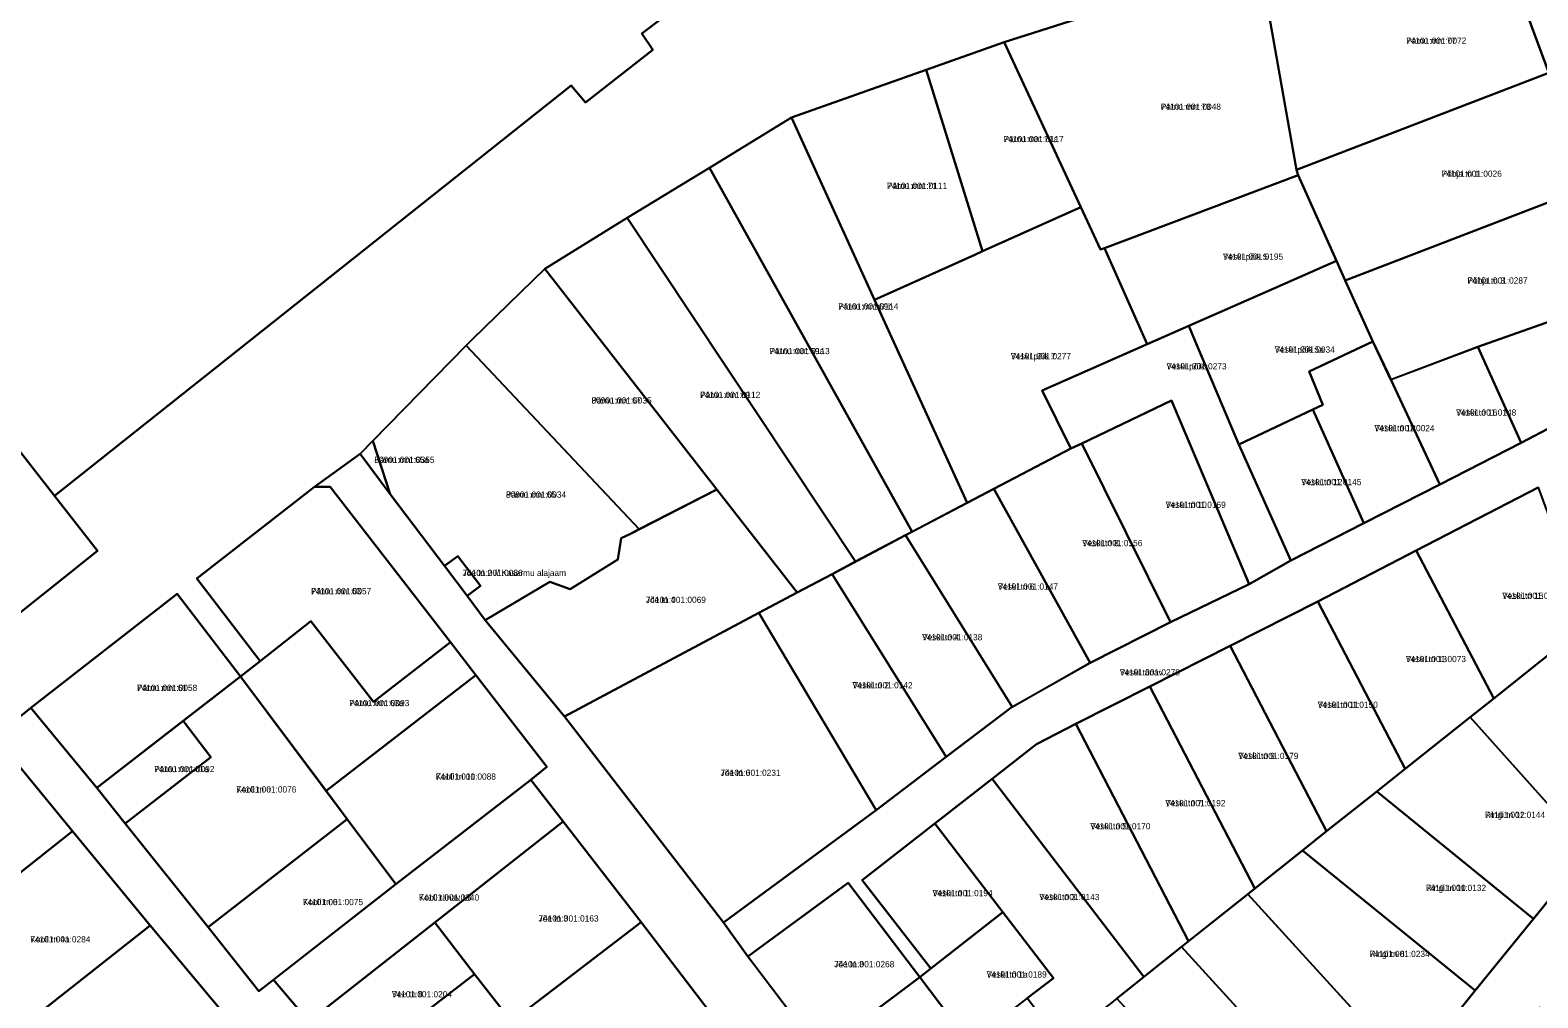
# Model space of a CAD drawing. Extents: x 524000 to 564260, y 6469338 to 6496391.
# Drawn here: x 538611.4 to 538974.9, y 6474369 to 6474602.3 of the extents above; entities that cross this region are included whole.
import ezdxf

# ---------------------------------------------------------------- set-up
doc = ezdxf.new("R2010")
doc.units = 0
for name, color, linetype in [('L_AADRESS', 7, 'Continuous'), ('PIIR', 7, 'Continuous'), ('TUNNUS', 7, 'Continuous')]:
    doc.layers.add(name, color=color, linetype=linetype)

msp = doc.modelspace()

# ---------------------------------------------------------------- linework, layer by layer
at = {"layer": 'PIIR'}
for points in [[(538977.59, 6474592), (538963.74, 6474629.42), (538971.75, 6474634.3), (538987.81, 6474590.76), (538994.7, 6474571.49), (539004.64, 6474545), (539014.72, 6474516.14), (539033.35, 6474462.51), (539027.05, 6474453.49), (539019.89, 6474474.48), (539007.32, 6474508.78), (539002.63, 6474519.46), (538996.03, 6474538.66), (538994.03, 6474544.04), (538987.03, 6474564.43)], [(538908.23, 6474616.82), (538963.74, 6474629.42), (538977.59, 6474592), (538916.78, 6474568.64)], [(538869.49, 6474549.4), (538846.25, 6474599.4), (538877.81, 6474609.46), (538908.23, 6474616.82), (538916.78, 6474568.64), (538917.16, 6474567.35), (538870.48, 6474549.77)], [(538846.25, 6474599.4), (538864.74, 6474559.62), (538841.01, 6474548.99), (538827.46, 6474592.74)], [(538827.46, 6474592.74), (538841.01, 6474548.99), (538839.19, 6474548.17), (538814.99, 6474537.32), (538795, 6474581.23)], [(538926.41, 6474546.71), (538917.16, 6474567.35), (538916.78, 6474568.64), (538977.59, 6474592), (538987.03, 6474564.43), (538928.49, 6474541.92)], [(538795, 6474581.23), (538814.99, 6474537.32), (538837.3, 6474488.32), (538824.03, 6474481.37), (538775.16, 6474569.14)], [(538775.16, 6474569.14), (538824.03, 6474481.37), (538822.42, 6474480.53), (538810.38, 6474474.16), (538755.33, 6474557.04)], [(538880.7, 6474526.56), (538870.48, 6474549.77), (538917.16, 6474567.35), (538926.41, 6474546.71), (538911.31, 6474540.02), (538890.78, 6474530.99)], [(538987.03, 6474564.43), (538994.03, 6474544.04), (538986.96, 6474541.66), (538988.92, 6474536.01), (538960.51, 6474525.92), (538939.48, 6474517.96), (538938.82, 6474519.38), (538935.17, 6474527.22), (538928.49, 6474541.92)], [(538864.74, 6474559.62), (538869.49, 6474549.4), (538870.48, 6474549.77), (538880.7, 6474526.56), (538855.4, 6474515.43), (538862.33, 6474501.42), (538843.78, 6474491.71), (538837.3, 6474488.32), (538814.99, 6474537.32), (538839.19, 6474548.17), (538841.01, 6474548.99)], [(538755.33, 6474557.04), (538810.38, 6474474.16), (538804.74, 6474471.17), (538796.35, 6474466.73), (538776.93, 6474491.57), (538735.48, 6474544.8)], [(538717.96, 6474527.75), (538735.48, 6474544.8), (538776.93, 6474491.57), (538758.26, 6474481.99), (538716.53, 6474526.3)], [(538892.33, 6474527.3), (538890.78, 6474530.99), (538911.31, 6474540.02), (538926.41, 6474546.71), (538928.49, 6474541.92), (538935.17, 6474527.22), (538919.76, 6474519.97), (538923.13, 6474511.97), (538920.67, 6474510.81), (538902.83, 6474502.37)], [(538970.95, 6474502.8), (538960.51, 6474525.92), (538988.92, 6474536.01), (538996.03, 6474538.66), (539002.63, 6474519.46)], [(538890.78, 6474530.99), (538892.33, 6474527.3), (538902.83, 6474502.37), (538915.35, 6474474.4), (538905.34, 6474468.72), (538886.57, 6474512.99), (538865.01, 6474502.62), (538862.33, 6474501.42), (538855.4, 6474515.43), (538880.7, 6474526.56)], [(538693.98, 6474503.28), (538716.53, 6474526.3), (538758.26, 6474481.99), (538755.96, 6474480.81), (538753.9, 6474479.81), (538753.05, 6474474.64), (538741.56, 6474467.55), (538736.69, 6474469.28), (538721.09, 6474460.07), (538716.71, 6474465.91), (538719.93, 6474468.3), (538714.51, 6474475.51), (538711.31, 6474473.12), (538698.2, 6474490.47), (538694.06, 6474503.04)], [(538920.67, 6474510.81), (538923.13, 6474511.97), (538919.76, 6474519.97), (538935.17, 6474527.22), (538938.84, 6474519.5), (538939.51, 6474518.1), (538951.3, 6474492.78), (538932.95, 6474483.42)], [(538939.51, 6474518.1), (538960.51, 6474525.92), (538970.95, 6474502.8), (538951.3, 6474492.78)], [(538544.83, 6474476), (538596.73, 6474516.27), (538617.2, 6474490.06), (538627.58, 6474476.75), (538576.39, 6474435.94)], [(538886.57, 6474512.99), (538905.34, 6474468.72), (538886.35, 6474459.58), (538865.01, 6474502.62)], [(538902.83, 6474502.37), (538920.67, 6474510.81), (538932.95, 6474483.42), (538915.35, 6474474.4)], [(538693.98, 6474503.28), (538698.2, 6474490.47), (538690.92, 6474500.18)], [(538865.01, 6474502.62), (538886.35, 6474459.58), (538867, 6474449.77), (538843.78, 6474491.71), (538862.33, 6474501.42)], [(538679.97, 6474492.17), (538683.68, 6474492.23), (538712.7, 6474454.73), (538694.12, 6474440.35), (538679.06, 6474459.77), (538666.8, 6474450.2), (538651.56, 6474470.07)], [(538796.35, 6474466.73), (538787.06, 6474461.85), (538740.26, 6474436.84), (538721.09, 6474460.07), (538736.69, 6474469.28), (538741.56, 6474467.55), (538753.05, 6474474.64), (538753.9, 6474479.81), (538755.96, 6474480.81), (538776.93, 6474491.57)], [(538837.3, 6474488.32), (538843.78, 6474491.71), (538867, 6474449.77), (538847.55, 6474438.66), (538848.21, 6474439.16), (538822.42, 6474480.53)], [(538945.62, 6474476.84), (538975.04, 6474492.07), (538985.81, 6474462.76), (538987.09, 6474459.29), (538964.31, 6474441.18)], [(538832.26, 6474427.06), (538804.74, 6474471.17), (538822.42, 6474480.53), (538848.21, 6474439.16)], [(538714.51, 6474475.51), (538719.93, 6474468.3), (538716.71, 6474465.91), (538711.31, 6474473.12)], [(538945.62, 6474476.84), (538964.31, 6474441.18), (538958.66, 6474436.69), (538942.98, 6474424.22), (538921.91, 6474464.57)], [(538796.35, 6474466.73), (538804.74, 6474471.17), (538832.26, 6474427.06), (538815.41, 6474414.27), (538787.06, 6474461.85)], [(538646.83, 6474466.37), (538662.08, 6474446.5), (538627.44, 6474419.6), (538611.51, 6474438.94)], [(538921.91, 6474464.57), (538942.98, 6474424.22), (538936.1, 6474418.76), (538924, 6474409.14), (538900.73, 6474453.86)], [(538740.26, 6474436.84), (538787.06, 6474461.85), (538815.41, 6474414.27), (538778.57, 6474387.15)], [(538712.7, 6474454.73), (538718.82, 6474446.82), (538682.73, 6474418.87), (538662.08, 6474446.5), (538666.8, 6474450.2), (538679.06, 6474459.77), (538694.12, 6474440.35)], [(538964.31, 6474441.18), (538987.09, 6474459.29), (539000.29, 6474420.56), (538987.35, 6474404.61), (538958.66, 6474436.69)], [(538881.4, 6474444.06), (538900.73, 6474453.86), (538924, 6474409.14), (538918.21, 6474404.53), (538906.69, 6474395.37)], [(538634.3, 6474411), (538654.9, 6474427), (538648.29, 6474435.79), (538662.08, 6474446.5), (538687.82, 6474412.06), (538654.26, 6474386)], [(538687.82, 6474412.06), (538682.73, 6474418.87), (538718.82, 6474446.82), (538735.95, 6474424.68), (538732.1, 6474421.56), (538699.57, 6474396.35)], [(538881.4, 6474444.06), (538906.69, 6474395.37), (538904.98, 6474394), (538890.71, 6474382.65), (538863.52, 6474435.09)], [(538627.44, 6474419.6), (538648.29, 6474435.79), (538654.9, 6474427), (538634.3, 6474411)], [(538942.98, 6474424.22), (538958.66, 6474436.69), (538987.35, 6474404.61), (538973.92, 6474388.05), (538936.1, 6474418.76)], [(538602.88, 6474431.92), (538621.59, 6474409.2), (538584.02, 6474379.46), (538566.97, 6474403.52)], [(538854.08, 6474430.11), (538863.52, 6474435.09), (538890.71, 6474382.65), (538889, 6474381.29), (538879.91, 6474374.06), (538843.32, 6474421.75)], [(538678.55, 6474363.31), (538670.05, 6474373.34), (538699.57, 6474396.35), (538732.1, 6474421.56), (538739.91, 6474411.48), (538708.99, 6474387.13)], [(538829.52, 6474411.02), (538843.32, 6474421.75), (538879.91, 6474374.06), (538873.38, 6474368.86), (538859.93, 6474358.17), (538851.8, 6474368.88), (538858.13, 6474373.74), (538845.95, 6474389.6)], [(538936.1, 6474418.76), (538973.92, 6474388.05), (538959.85, 6474370.72), (538918.21, 6474404.53), (538924, 6474409.14)], [(538699.57, 6474396.35), (538666.54, 6474370.61), (538654.26, 6474386), (538687.82, 6474412.06)], [(538718.49, 6474374.72), (538708.99, 6474387.13), (538739.91, 6474411.48), (538758.7, 6474387.21), (538727.46, 6474363.28)], [(538829.52, 6474411.02), (538845.95, 6474389.6), (538828.55, 6474376.07), (538811.98, 6474397.38)], [(538621.59, 6474409.2), (538640.34, 6474386.45), (538601, 6474355.48), (538592.29, 6474367.79), (538584.02, 6474379.46)], [(538906.69, 6474395.37), (538918.21, 6474404.53), (538959.85, 6474370.72), (538954.95, 6474364.67), (538942.26, 6474353.11), (538904.98, 6474394)], [(538808.62, 6474396.72), (538825.87, 6474373.98), (538801.88, 6474355.97), (538784.45, 6474378.94)], [(538904.98, 6474394), (538942.26, 6474353.11), (538927.21, 6474339.38), (538889, 6474381.29)], [(538825.87, 6474373.98), (538828.55, 6474376.07), (538845.95, 6474389.6), (538858.13, 6474373.74), (538851.8, 6474368.88), (538837.92, 6474358.11)], [(538640.34, 6474386.45), (538658.76, 6474364.28), (538617.77, 6474331.89), (538601, 6474355.48)], [(538678.55, 6474363.31), (538708.99, 6474387.13), (538718.49, 6474374.72), (538687.93, 6474351.07)], [(538737.46, 6474350.11), (538728.06, 6474362.51), (538727.46, 6474363.28), (538758.7, 6474387.21), (538777.23, 6474363), (538746, 6474339.05)], [(538889, 6474381.29), (538927.21, 6474339.38), (538912.49, 6474325.97), (538873.38, 6474368.86)], [(538687.93, 6474351.07), (538718.49, 6474374.72), (538727.46, 6474363.28), (538728.06, 6474362.51), (538697.33, 6474338.86)], [(538801.88, 6474355.97), (538825.87, 6474373.98), (538837.92, 6474358.11), (538813.97, 6474340.04)]]:
    msp.add_lwpolyline(points, close=True, dxfattribs=at)
for points in [[(538793.63, 6474627.81), (538758.87, 6474601.52), (538761.55, 6474597.57), (538745.3, 6474584.88), (538741.81, 6474589.01), (538617.2, 6474490.06), (538596.73, 6474516.27), (538557.75, 6474565.87), (538501.44, 6474521.28), (538496, 6474516.95), (538416.66, 6474453.86), (538401.82, 6474471.42)], [(538576.39, 6474435.94), (538627.58, 6474476.75), (538617.2, 6474490.06), (538741.81, 6474589.01), (538745.3, 6474584.88), (538761.55, 6474597.57), (538758.87, 6474601.52), (538793.63, 6474627.81)], [(538877.81, 6474609.46), (538846.25, 6474599.4), (538827.46, 6474592.74), (538795, 6474581.23), (538775.16, 6474569.14), (538755.33, 6474557.04), (538735.48, 6474544.8), (538717.96, 6474527.75), (538716.53, 6474526.3), (538693.98, 6474503.28), (538690.92, 6474500.18), (538679.97, 6474492.17), (538651.56, 6474470.07), (538666.8, 6474450.2), (538662.08, 6474446.5), (538646.83, 6474466.37), (538611.51, 6474438.94), (538602.88, 6474431.92)], [(538975.04, 6474492.07), (538945.62, 6474476.84), (538921.91, 6474464.57), (538900.73, 6474453.86), (538881.4, 6474444.06), (538863.52, 6474435.09), (538854.08, 6474430.11), (538843.32, 6474421.75), (538829.52, 6474411.02), (538811.98, 6474397.38), (538828.55, 6474376.07), (538825.87, 6474373.98), (538808.62, 6474396.72), (538784.45, 6474378.94), (538778.57, 6474387.15), (538815.41, 6474414.27), (538832.26, 6474427.06), (538848.21, 6474439.16), (538867, 6474449.77), (538886.35, 6474459.58), (538905.34, 6474468.72), (538915.35, 6474474.4), (538932.95, 6474483.42), (538951.3, 6474492.78), (538970.95, 6474502.8), (539002.63, 6474519.46)], [(538777.23, 6474363), (538758.7, 6474387.21), (538739.91, 6474411.48), (538732.1, 6474421.56), (538735.95, 6474424.68), (538718.82, 6474446.82), (538712.7, 6474454.73), (538683.68, 6474492.23), (538679.97, 6474492.17), (538690.92, 6474500.18), (538698.2, 6474490.47), (538711.31, 6474473.12), (538716.71, 6474465.91), (538721.09, 6474460.07), (538740.26, 6474436.84), (538778.57, 6474387.15), (538784.45, 6474378.94), (538785.84, 6474377.1), (538801.88, 6474355.97)], [(538658.76, 6474364.28), (538640.34, 6474386.45), (538621.59, 6474409.2), (538602.88, 6474431.92), (538611.51, 6474438.94), (538627.44, 6474419.6), (538634.3, 6474411), (538654.26, 6474386), (538666.54, 6474370.61), (538670.05, 6474373.34), (538678.55, 6474363.31)], [(538975.53, 6474366.77), (538964.56, 6474353.26), (538949.92, 6474339.62), (538935.3, 6474326.14), (538924.33, 6474315.93), (538913.04, 6474305.42), (538891.04, 6474284.83), (538870.47, 6474265.69), (538861.54, 6474277.8), (538896.53, 6474310.28), (538912.49, 6474325.97), (538927.21, 6474339.38), (538942.26, 6474353.11), (538954.95, 6474364.67), (538959.85, 6474370.72), (538973.92, 6474388.05), (538987.35, 6474404.61)]]:
    msp.add_lwpolyline(points, dxfattribs=at)

# ---------------------------------------------------------------- texts
at = {"layer": 'L_AADRESS'}
for s, p in [('Pärnu mnt 77', (538943.19, 6474599.03)), ('Pärnu mnt 73', (538884.02, 6474583.11)), ('Pärnu mnt 71a', (538846.1, 6474575.31)), ('Põhja tn 1', (538951.75, 6474566.96)), ('Pärnu mnt 71', (538818, 6474564.03)), ('Veski põik 5', (538899.01, 6474546.96)), ('Põhja tn 3', (538957.97, 6474541.2)), ('Pärnu mnt 69b', (538806.23, 6474534.95)), ('Veski põik 5a', (538911.48, 6474524.54)), ('Pärnu mnt 69a', (538789.68, 6474524.19)), ('Veski põik 7', (538847.85, 6474522.94)), ('Veski põik', (538885.38, 6474520.51)), ('Pärnu mnt 67', (538746.73, 6474512.29)), ('Pärnu mnt 69', (538772.93, 6474513.62)), ('Veski tn 16', (538955.23, 6474509.37)), ('Veski tn 14', (538935.53, 6474505.6)), ('Pärnu mnt 65a', (538694.37, 6474497.98)), ('Veski tn 12', (538917.89, 6474492.6)), ('Pärnu mnt 65', (538726.12, 6474489.58)), ('Veski tn 10', (538885.18, 6474487.13)), ('Veski tn 8', (538865.07, 6474477.89)), ('Jõe tn 2 // Kasarmu alajaam', (538715.62, 6474470.7)), ('Veski tn 6', (538844.71, 6474467.4)), ('Pärnu mnt 63', (538679.11, 6474466.29)), ('Jõe tn 4', (538759.82, 6474464.21)), ('Veski tn 15', (538966.36, 6474465.19)), ('Veski tn 4', (538826.48, 6474455.18)), ('Veski tn 13', (538943.11, 6474449.93)), ('Veski tänav', (538874.12, 6474446.72)), ('Pärnu mnt 61', (538637.14, 6474442.99)), ('Veski tn 2', (538809.66, 6474443.6)), ('Pärnu mnt 63a', (538688.29, 6474439.32)), ('Veski tn 11', (538921.85, 6474438.9)), ('Veski tn 9', (538902.7, 6474426.56)), ('Pärnu mnt 61a', (538641.29, 6474423.4)), ('Kooli tn 10', (538709.18, 6474421.59)), ('Jõe tn 6', (538777.83, 6474422.51)), ('Kooli tn 6', (538661.06, 6474418.49)), ('Veski tn 7', (538885.11, 6474415.19)), ('Ringi tn 12', (538962.19, 6474412.37)), ('Veski tn 5', (538867.02, 6474409.61)), ('Ringi tn 10', (538947.97, 6474394.74)), ('Kooli tn 8', (538677.13, 6474391.33)), ('Kooli tänav L6', (538705.14, 6474392.43)), ('Veski tn 1', (538828.96, 6474393.49)), ('Veski tn 3', (538854.71, 6474392.54)), ('Jõe tn 3', (538733.94, 6474387.38)), ('Kooli tn 4a', (538611.39, 6474382.34)), ('Jõe tn 8', (538805.25, 6474376.34)), ('Ringi tn 8', (538934.35, 6474378.82)), ('Veski tn 1a', (538842, 6474373.86)), ('Vee tn 8', (538698.59, 6474369.1))]:
    msp.add_text(s, height=1.5, dxfattribs=at).set_placement(p)
at = {"layer": 'TUNNUS'}
for s, p in [('74101:001:0072', (538943.19, 6474599.03)), ('74101:001:0048', (538884.02, 6474583.11)), ('74101:001:0117', (538846.1, 6474575.31)), ('74101:001:0026', (538951.75, 6474566.96)), ('74101:001:0111', (538818, 6474564.03)), ('74101:001:0195', (538899.01, 6474546.96)), ('74101:001:0287', (538957.97, 6474541.2)), ('74101:001:0114', (538806.23, 6474534.95)), ('74101:001:0113', (538789.68, 6474524.19)), ('74101:001:0277', (538847.85, 6474522.94)), ('74101:001:0034', (538911.48, 6474524.54)), ('74101:001:0273', (538885.38, 6474520.51)), ('80901:001:0035', (538746.73, 6474512.29)), ('74101:001:0112', (538772.93, 6474513.62)), ('74101:001:0148', (538955.23, 6474509.37)), ('74101:001:0024', (538935.53, 6474505.6)), ('80901:001:0355', (538694.37, 6474497.98)), ('74101:001:0145', (538917.89, 6474492.6)), ('80901:001:0034', (538726.12, 6474489.58)), ('74101:001:0169', (538885.18, 6474487.13)), ('74101:001:0156', (538865.07, 6474477.89)), ('74101:001:0086', (538715.62, 6474470.7)), ('74101:001:0147', (538844.71, 6474467.4)), ('74101:001:0057', (538679.11, 6474466.29)), ('74101:001:0069', (538759.82, 6474464.21)), ('74101:001:0146', (538966.36, 6474465.19)), ('74101:001:0138', (538826.48, 6474455.18)), ('74101:001:0073', (538943.11, 6474449.93)), ('74101:001:0278', (538874.12, 6474446.72)), ('74101:001:0058', (538637.14, 6474442.99)), ('74101:001:0142', (538809.66, 6474443.6)), ('74101:001:0093', (538688.29, 6474439.32)), ('74101:001:0150', (538921.85, 6474438.9)), ('74101:001:0179', (538902.7, 6474426.56)), ('74101:001:0092', (538641.29, 6474423.4)), ('74101:001:0088', (538709.18, 6474421.59)), ('74101:001:0231', (538777.83, 6474422.51)), ('74101:001:0076', (538661.06, 6474418.49)), ('74101:001:0192', (538885.11, 6474415.19)), ('74101:001:0144', (538962.19, 6474412.37)), ('74101:001:0170', (538867.02, 6474409.61)), ('74101:001:0132', (538947.97, 6474394.74)), ('74101:001:0075', (538677.13, 6474391.33)), ('74101:001:0340', (538705.14, 6474392.43)), ('74101:001:0194', (538828.96, 6474393.49)), ('74101:001:0143', (538854.71, 6474392.54)), ('74101:001:0163', (538733.94, 6474387.38)), ('74101:001:0284', (538611.39, 6474382.34)), ('74101:001:0268', (538805.25, 6474376.34)), ('74101:001:0234', (538934.35, 6474378.82)), ('74101:001:0189', (538842, 6474373.86)), ('74101:001:0204', (538698.59, 6474369.1))]:
    msp.add_text(s, height=1.5, dxfattribs=at).set_placement(p)

doc.saveas('drawing.dxf')
